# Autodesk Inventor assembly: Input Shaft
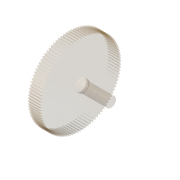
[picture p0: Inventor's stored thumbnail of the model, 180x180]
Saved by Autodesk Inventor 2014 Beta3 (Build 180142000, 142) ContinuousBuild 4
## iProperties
Created: 2011-01
Part Number: Input Shaft
Document SubType Name: Assembly
Designer: Beta-8540w
ClientObjectVersion: 1
Author: Beta-8540w
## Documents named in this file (2)
- C:\Inventor 2014 Essentials\Assemblies\Chapter 09\Design Accelerators\Shaft c09-04.iam
- C:\Inventor 2014 Essentials\Assemblies\Chapter 09\Design Accelerators\Shaft c09-04.ipt
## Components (1 placed, 1 different names)
1. Input Shaft:1
